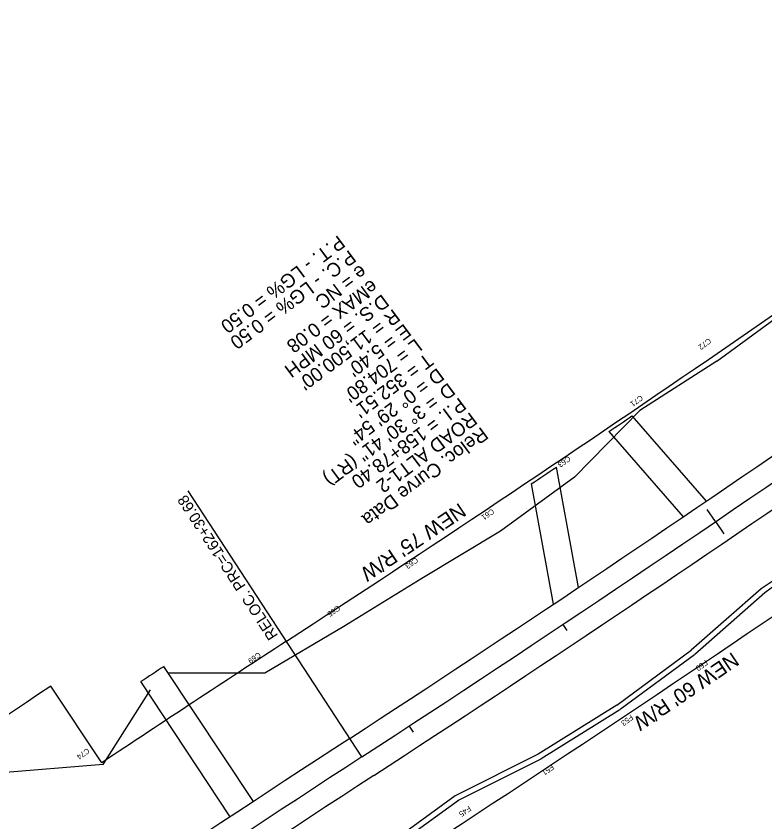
# Model space of a CAD drawing. Extents: x 1469024 to 1473560, y 1105695 to 1109739.
# Drawn here: x 1471479.1 to 1471885.6, y 1108041.8 to 1108479.6 of the extents above; entities that cross this region are included whole.
import ezdxf

# ---------------------------------------------------------------- set-up
doc = ezdxf.new("R2010")
doc.units = 0
for name, color, linetype in [('RD_HC_CL_Rel', 7, 'Continuous'), ('RD_HC_Data_Rel', 7, 'Continuous'), ('RD_HC_Data_Tic_Rel', 7, 'Continuous'), ('RD_PD_CstnLmt', 7, 'Continuous'), ('RD_PD_CstnLmt_TX', 7, 'Continuous'), ('RD_PD_DR_ErosCtrl', 7, 'Continuous'), ('RD_PD_Driveway', 7, 'Continuous'), ('RD_PD_Final_TrvlWay', 7, 'Continuous'), ('RD_PD_RW', 7, 'Continuous'), ('RD_PD_RW_TX', 7, 'Continuous')]:
    doc.layers.add(name, color=color, linetype=linetype)

msp = doc.modelspace()

# ---------------------------------------------------------------- linework, layer by layer
at = {"layer": 'RD_HC_CL_Rel'}
for centre, start, end in [((1465390.13, 1117713.11), 303.079489, 306.590952), ((1477943.58, 1098441.09), 123.079489, 126.41418)]:
    msp.add_arc(centre, 11500, start, end, dxfattribs=at)
at = {"layer": 'RD_HC_Data_Rel'}
msp.add_line((1471666.85, 1108077.1), (1471572.62, 1108221.76), dxfattribs=at)
at = {"layer": 'RD_HC_Data_Tic_Rel'}
for p, q in [((1471858.87, 1108204.94), (1471854.37, 1108211.55)), ((1471858.87, 1108204.94), (1471863.37, 1108198.33)), ((1471775.95, 1108149.05), (1471778.17, 1108145.72)), ((1471692.54, 1108093.88), (1471694.73, 1108090.54))]:
    msp.add_line(p, q, dxfattribs=at)
at = {"layer": 'RD_PD_CstnLmt'}
for p, q in [((1471859.64, 1108292.15), (1471899.66, 1108321.63)), ((1471859.64, 1108292.15), (1471817.81, 1108265.3)), ((1471817.81, 1108265.3), (1471782.26, 1108229.15)), ((1471782.26, 1108229.15), (1471742.08, 1108199.78)), ((1471742.08, 1108199.78), (1471699.47, 1108174.04)), ((1471699.47, 1108174.04), (1471657.12, 1108147.95)), ((1471657.12, 1108147.95), (1471614.08, 1108122.53)), ((1471805.24, 1108105.18), (1471845.71, 1108135.01)), ((1471614.08, 1108122.53), (1471562.09, 1108122.61)), ((1471526.3, 1108072.88), (1471552.08, 1108113.59)), ((1471805.24, 1108105.18), (1471762.65, 1108078.52)), ((1471762.65, 1108078.52), (1471717.45, 1108055.86)), ((1471526.3, 1108072.88), (1471468.75, 1108068.28)), ((1471717.45, 1108055.86), (1471676.93, 1108026.38))]:
    msp.add_line(p, q, dxfattribs=at)
for points in [[(1471925.51, 1108196.23), (1471883.66, 1108168.5)], [(1471883.66, 1108168.5), (1471845.71, 1108135.01)], [(1471883.66, 1108168.5), (1471845.71, 1108135.01)]]:
    msp.add_lwpolyline(points, dxfattribs=at)
at = {"layer": 'RD_PD_DR_ErosCtrl'}
for p, q in [((1471925.51, 1108196.23), (1471885.65, 1108166.25)), ((1471885.65, 1108166.25), (1471847.69, 1108132.76)), ((1471847.49, 1108132.6), (1471807.02, 1108102.77)), ((1471806.83, 1108102.64), (1471764.24, 1108075.98)), ((1471763.99, 1108075.84), (1471718.8, 1108053.18)), ((1471719.22, 1108053.43), (1471678.7, 1108023.96))]:
    msp.add_line(p, q, dxfattribs=at)
at = {"layer": 'RD_PD_Driveway'}
for p, q in [((1471813.5, 1108262.37), (1471853.8, 1108216)), ((1471801, 1108253.88), (1471841.31, 1108207.51)), ((1471772.42, 1108234.58), (1471784.34, 1108169.1)), ((1471758.84, 1108225.44), (1471770.74, 1108160)), ((1471607.94, 1108052.85), (1471559.41, 1108126.26)), ((1471595.42, 1108044.58), (1471546.9, 1108117.99))]:
    msp.add_line(p, q, dxfattribs=at)
for centre, radius, start, end in [((1465390.13, 1117713.11), 11427, 304.126935, 304.202684), ((1465390.13, 1117713.11), 11427, 303.871946, 303.954022), ((1477943.58, 1098441.09), 11600, 123.391635, 123.465724)]:
    msp.add_arc(centre, radius, start, end, dxfattribs=at)
at = {"layer": 'RD_PD_Final_TrvlWay'}
for centre, radius, start, end in [((1465390.13, 1117713.11), 11488, 303.079489, 306.221713), ((1465390.13, 1117713.11), 11512, 303.079489, 306.221713), ((1477943.58, 1098441.09), 11512, 123.079489, 126.41418), ((1477943.58, 1098441.09), 11488, 123.079489, 126.41418)]:
    msp.add_arc(centre, radius, start, end, dxfattribs=at)
at = {"layer": 'RD_PD_RW'}
msp.add_line((1471525.63, 1108073.88), (1471497.91, 1108115.49), dxfattribs=at)
for centre, radius, start, end in [((1465390.13, 1117713.11), 11425, 303.079489, 305.842989), ((1465390.13, 1117713.11), 11560, 302.674208, 304.226672), ((1477943.58, 1098441.09), 11575, 123.079489, 123.673947), ((1477943.58, 1098441.09), 11625, 123.673947, 126.165068)]:
    msp.add_arc(centre, radius, start, end, dxfattribs=at)

# ---------------------------------------------------------------- texts
at = {"layer": 'RD_HC_Data_Rel'}
for s, height, rotation, p in [('P.T. - LG% = 0.50', 7.5, 216.7283, (1471654.03, 1108360.9)), ('P.C. - LG% = 0.50', 7.5, 216.7283, (1471660.01, 1108352.89)), ('e = NC', 7.5, 216.7283, (1471665.99, 1108344.87)), ('eMAX = 0.08', 7.5, 216.7283, (1471671.97, 1108336.86)), ('D.S. = 60 MPH', 7.5, 216.7283, (1471677.95, 1108328.84)), ("R = 11,500.00'", 7.5, 216.7283, (1471683.93, 1108320.83)), ("E = 5.40'", 7.5, 216.7283, (1471689.91, 1108312.81)), ("L = 704.80'", 7.5, 216.7283, (1471695.9, 1108304.8)), ("T = 352.51'", 7.5, 216.7283, (1471701.88, 1108296.78)), ('D = 0%%d 29\' 54"', 7.5, 216.7283, (1471707.86, 1108288.77)), ('D', 7.5, 216.7283, (1471713.84, 1108280.75)), ('    = 3%%d 30\' 41" (RT)', 7.5, 216.7283, (1471713.84, 1108280.75)), ('P.I. = 158+78.40', 7.5, 216.7283, (1471719.82, 1108272.74)), ('ROAD ALT1-2', 7.5, 216.7283, (1471725.8, 1108264.73)), ('Reloc. Curve Data', 7.5, 216.7283, (1471731.78, 1108256.71)), ('RELOC. PRC=162+30.68', 6, 123.0795, (1471621.51, 1108143.04))]:
    msp.add_text(s, height=height, rotation=rotation, dxfattribs=at).set_placement(p)
at = {"layer": 'RD_PD_CstnLmt_TX'}
for s, rotation, p in [('C72', 216.2385, (1471855.12, 1108304.82)), ('C71', 216.2385, (1471818.1, 1108273.9)), ('C63', 214.9929, (1471778.87, 1108240.81)), ('C61', 214.9929, (1471737.41, 1108212.16)), ('C63', 214.9929, (1471696.09, 1108185.7)), ('C65', 214.7438, (1471653.78, 1108159.63)), ('C69', 214.7438, (1471610.74, 1108134.21)), ('F50', 216.2385, (1471853.28, 1108130.03)), ('F53', 216.2385, (1471812.81, 1108100.2)), ('C74', 215.1854, (1471517.67, 1108082.08)), ('F51', 214.9929, (1471769.88, 1108073.21)), ('F45', 214.7438, (1471724.89, 1108050.68))]:
    msp.add_text(s, height=3, rotation=rotation, dxfattribs=at).set_placement(p)
at = {"layer": 'RD_PD_RW_TX'}
for s, p in [("NEW 75' R/W", (1471719.76, 1108215.44)), ("NEW 60' R/W", (1471867.96, 1108134.32))]:
    msp.add_text(s, height=8, rotation=214.0223, dxfattribs=at).set_placement(p)

doc.saveas('drawing.dxf')
